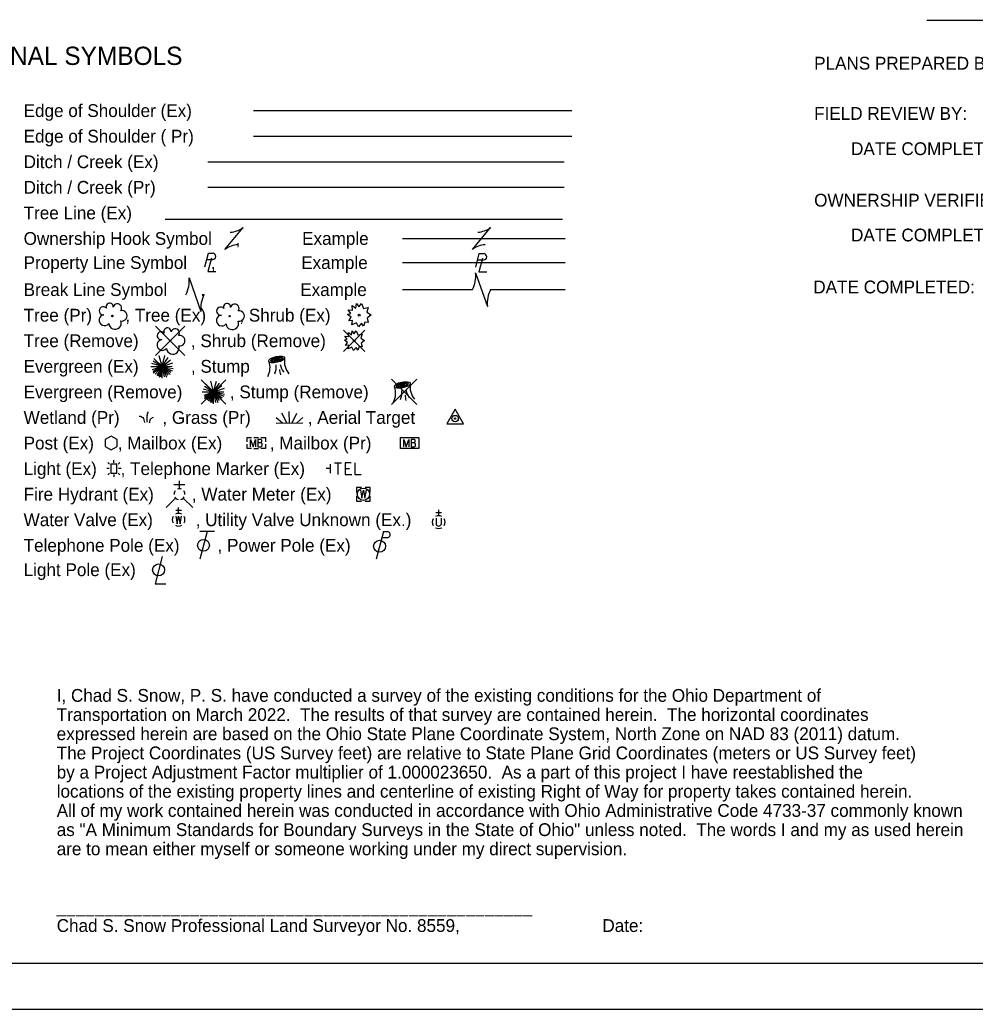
# Model space of a CAD drawing. Extents: x 0 to 59.1, y -2.4 to 22.
# Drawn here: x 16.87 to 27.33, y 0 to 10.83 of the extents above; entities that cross this region are included whole.
import ezdxf

# ---------------------------------------------------------------- set-up
doc = ezdxf.new("R2010")
doc.units = 0
for name, color, linetype in [('SH_Border', 7, 'Continuous'), ('SH_Cut_Line', 7, 'Continuous'), ('SH_Text', 7, 'Continuous')]:
    doc.layers.add(name, color=color, linetype=linetype)

msp = doc.modelspace()

# ---------------------------------------------------------------- linework, layer by layer
at = {"layer": 'SH_Border'}
msp.add_lwpolyline([(1.5, 21.5), (33.5, 21.5), (33.5, 0.5), (1.5, 0.5)], close=True, dxfattribs=at)
at = {"layer": 'SH_Cut_Line'}
msp.add_lwpolyline([(0, 0), (34, 0), (34, 22), (0, 22)], close=True, dxfattribs=at)
at = {"layer": 'SH_Text'}
for p, q in [((26.802, 10.829), (30.732, 10.829)), ((19.433, 9.839), (22.917, 9.839)), ((19.433, 9.559), (22.917, 9.559)), ((18.933, 9.279), (22.833, 9.279)), ((18.933, 8.999), (22.833, 8.999)), ((18.465, 8.649), (22.815, 8.649)), ((19.12, 8.319), (19.32, 8.559)), ((21.829, 8.319), (22.029, 8.559)), ((19.22, 8.439), (19.22, 8.439)), ((21.063, 8.439), (22.845, 8.439)), ((21.929, 8.439), (21.929, 8.439)), ((18.921, 8.208), (18.986, 8.208)), ((18.961, 8.177), (18.961, 8.177)), ((21.063, 8.175), (22.845, 8.175)), ((21.886, 8.204), (21.951, 8.204)), ((21.926, 8.173), (21.926, 8.173)), ((21.864, 8.063), (21.994, 7.695)), ((18.728, 8.008), (18.858, 7.64)), ((18.793, 7.824), (18.793, 7.824)), ((21.063, 7.879), (21.829, 7.879)), ((21.929, 7.879), (21.929, 7.879)), ((22.029, 7.879), (22.845, 7.879)), ((18.361, 7.48), (18.682, 7.159)), ((18.682, 7.48), (18.361, 7.159)), ((20.42, 7.435), (20.652, 7.203)), ((20.652, 7.435), (20.42, 7.203)), ((18.521, 7.319), (18.521, 7.319)), ((20.536, 7.319), (20.536, 7.319)), ((18.432, 7.039), (18.401, 7.154)), ((18.432, 7.039), (18.463, 7.156)), ((18.432, 7.039), (18.321, 7.069)), ((18.432, 7.039), (18.334, 7.096)), ((18.432, 7.039), (18.344, 7.126)), ((18.432, 7.039), (18.498, 7.136)), ((18.432, 7.039), (18.523, 7.109)), ((18.432, 7.039), (18.55, 7.079)), ((18.308, 7.039), (18.432, 7.039)), ((18.432, 7.039), (18.324, 7)), ((18.432, 7.039), (18.332, 6.982)), ((18.432, 7.039), (18.334, 6.964)), ((18.432, 7.039), (18.358, 6.952)), ((18.432, 7.039), (18.374, 6.939)), ((18.432, 7.039), (18.39, 6.93)), ((18.432, 7.039), (18.4, 6.918)), ((18.432, 7.039), (18.418, 6.924)), ((18.432, 7.039), (18.544, 7.041)), ((18.432, 6.908), (18.432, 7.039)), ((18.432, 7.039), (18.455, 6.923)), ((18.432, 7.039), (18.48, 6.922)), ((18.432, 7.039), (18.495, 6.944)), ((18.432, 7.039), (18.521, 6.951)), ((18.432, 7.039), (18.527, 6.975)), ((18.432, 7.039), (18.543, 6.99)), ((18.432, 7.039), (18.552, 7.015)), ((19.705, 7.039), (19.705, 7.039)), ((18.862, 6.893), (19.129, 6.626)), ((19.129, 6.893), (18.862, 6.626)), ((18.996, 6.759), (18.908, 6.846)), ((18.996, 6.759), (18.965, 6.875)), ((18.996, 6.759), (19.027, 6.877)), ((18.996, 6.759), (19.062, 6.856)), ((18.996, 6.759), (19.087, 6.829)), ((20.942, 6.898), (21.22, 6.62)), ((21.22, 6.898), (20.942, 6.62)), ((18.872, 6.759), (18.996, 6.759)), ((18.996, 6.759), (18.885, 6.789)), ((18.996, 6.759), (18.888, 6.72)), ((18.996, 6.759), (18.896, 6.702)), ((18.996, 6.759), (18.898, 6.817)), ((18.996, 6.759), (18.898, 6.684)), ((18.996, 6.759), (18.922, 6.673)), ((18.996, 6.759), (18.938, 6.659)), ((18.996, 6.759), (18.954, 6.651)), ((18.996, 6.759), (18.964, 6.638)), ((18.996, 6.759), (18.982, 6.644)), ((18.996, 6.759), (19.114, 6.799)), ((18.996, 6.759), (19.108, 6.761)), ((18.996, 6.628), (18.996, 6.759)), ((18.996, 6.759), (19.019, 6.643)), ((18.996, 6.759), (19.044, 6.642)), ((18.996, 6.759), (19.059, 6.664)), ((18.996, 6.759), (19.085, 6.671)), ((18.996, 6.759), (19.091, 6.695)), ((18.996, 6.759), (19.107, 6.711)), ((18.996, 6.759), (19.116, 6.735)), ((18.996, 6.759), (18.996, 6.759)), ((21.081, 6.759), (21.081, 6.759)), ((21.081, 6.759), (21.081, 6.759)), ((19.797, 6.419), (19.745, 6.525)), ((19.827, 6.419), (19.825, 6.545)), ((19.857, 6.42), (19.906, 6.527)), ((19.749, 6.418), (19.68, 6.475)), ((19.681, 6.417), (19.973, 6.421)), ((19.906, 6.42), (19.973, 6.479)), ((19.438, 6.26), (19.489, 6.26)), ((19.464, 6.199), (19.464, 6.199)), ((21.142, 6.199), (21.142, 6.199)), ((19.438, 6.138), (19.489, 6.138)), ((17.856, 5.968), (17.838, 5.986)), ((17.904, 5.983), (17.904, 6.01)), ((17.971, 5.986), (17.952, 5.968)), ((20.277, 5.869), (20.277, 5.969)), ((17.852, 5.92), (17.826, 5.92)), ((17.856, 5.871), (17.838, 5.852)), ((17.904, 5.919), (17.904, 5.919)), ((17.904, 5.855), (17.904, 5.829)), ((17.971, 5.852), (17.952, 5.871)), ((17.983, 5.92), (17.956, 5.92)), ((20.277, 5.919), (20.227, 5.919)), ((18.682, 5.742), (18.562, 5.742)), ((18.622, 5.699), (18.622, 5.785)), ((18.623, 5.639), (18.623, 5.639)), ((18.623, 5.639), (18.623, 5.639)), ((20.636, 5.639), (20.636, 5.639)), ((18.58, 5.597), (18.476, 5.493)), ((18.665, 5.597), (18.769, 5.493)), ((18.645, 5.461), (18.582, 5.461)), ((18.613, 5.429), (18.613, 5.493)), ((21.491, 5.435), (21.428, 5.435)), ((21.46, 5.403), (21.46, 5.466)), ((18.613, 5.359), (18.613, 5.359)), ((21.432, 5.376), (21.432, 5.307)), ((21.46, 5.333), (21.46, 5.333)), ((21.487, 5.376), (21.487, 5.307)), ((19.006, 5.229), (18.846, 5.229)), ((18.926, 5.229), (18.846, 4.929)), ((20.855, 5.229), (20.775, 4.929)), ((20.855, 5.229), (20.898, 5.229)), ((20.838, 5.165), (20.898, 5.165))]:
    msp.add_line(p, q, dxfattribs=at)
for points in [[(18.9, 8.129), (18.939, 8.277), (18.99, 8.277)], [(21.865, 8.125), (21.904, 8.273), (21.956, 8.273)], [(18.974, 8.225), (18.935, 8.077), (19.022, 8.077)], [(21.94, 8.221), (21.9, 8.073), (21.988, 8.073)], [(20.585, 7.69), (20.615, 7.726), (20.636, 7.674), (20.69, 7.683), (20.673, 7.632), (20.72, 7.602), (20.678, 7.566), (20.69, 7.52), (20.652, 7.523), (20.636, 7.478), (20.615, 7.512), (20.581, 7.472), (20.559, 7.516), (20.508, 7.494), (20.518, 7.541), (20.477, 7.537), (20.501, 7.577), (20.463, 7.605), (20.5, 7.618), (20.469, 7.659), (20.516, 7.653), (20.514, 7.705), (20.552, 7.677), (20.562, 7.726), (20.585, 7.69)], [(20.532, 7.396), (20.558, 7.427), (20.576, 7.383), (20.622, 7.39), (20.608, 7.347), (20.648, 7.322), (20.611, 7.291), (20.622, 7.252), (20.59, 7.255), (20.576, 7.216), (20.558, 7.245), (20.529, 7.211), (20.511, 7.248), (20.468, 7.23), (20.476, 7.27), (20.441, 7.267), (20.461, 7.3), (20.429, 7.324), (20.46, 7.335), (20.434, 7.37), (20.474, 7.365), (20.473, 7.409), (20.505, 7.385), (20.513, 7.427), (20.532, 7.396)], [(17.811, 6.162), (17.876, 6.124), (17.941, 6.162), (17.941, 6.237), (17.876, 6.274), (17.811, 6.237), (17.811, 6.162)], [(19.364, 6.212), (19.364, 6.26), (19.413, 6.26)], [(19.413, 6.138), (19.364, 6.138), (19.364, 6.187)], [(19.399, 6.159), (19.399, 6.239), (19.428, 6.159), (19.456, 6.239), (19.456, 6.159)], [(19.515, 6.203), (19.518, 6.206), (19.52, 6.208), (19.521, 6.21), (19.522, 6.211), (19.523, 6.213), (19.524, 6.215), (19.525, 6.22), (19.525, 6.222), (19.525, 6.224), (19.525, 6.228), (19.523, 6.231), (19.521, 6.234), (19.518, 6.236), (19.516, 6.237), (19.515, 6.238), (19.511, 6.239), (19.481, 6.239), (19.481, 6.159), (19.515, 6.159), (19.52, 6.162), (19.523, 6.165), (19.526, 6.17), (19.528, 6.176), (19.529, 6.181), (19.529, 6.185), (19.528, 6.189), (19.525, 6.194), (19.522, 6.198), (19.515, 6.203), (19.481, 6.203)], [(19.514, 6.26), (19.564, 6.26), (19.564, 6.212)], [(19.564, 6.187), (19.564, 6.138), (19.514, 6.138)], [(21.077, 6.159), (21.077, 6.239), (21.106, 6.159), (21.134, 6.239), (21.134, 6.159)], [(21.193, 6.203), (21.196, 6.206), (21.198, 6.208), (21.2, 6.21), (21.2, 6.211), (21.201, 6.213), (21.202, 6.215), (21.203, 6.22), (21.203, 6.222), (21.203, 6.224), (21.203, 6.228), (21.201, 6.231), (21.2, 6.234), (21.196, 6.236), (21.194, 6.237), (21.193, 6.238), (21.19, 6.239), (21.159, 6.239), (21.159, 6.159), (21.193, 6.159), (21.198, 6.162), (21.201, 6.165), (21.205, 6.17), (21.207, 6.176), (21.207, 6.181), (21.207, 6.185), (21.206, 6.189), (21.203, 6.194), (21.2, 6.198), (21.193, 6.203), (21.159, 6.203)], [(20.318, 5.981), (20.396, 5.981)], [(20.357, 5.981), (20.357, 5.856)], [(20.503, 5.981), (20.435, 5.981), (20.435, 5.856), (20.508, 5.856)], [(20.542, 5.981), (20.542, 5.856), (20.61, 5.856)], [(20.435, 5.919), (20.483, 5.919)], [(20.616, 5.714), (20.561, 5.714), (20.561, 5.659)], [(20.603, 5.684), (20.619, 5.594), (20.636, 5.684), (20.653, 5.594), (20.669, 5.684)], [(20.711, 5.659), (20.711, 5.714), (20.656, 5.714)], [(20.561, 5.619), (20.561, 5.564), (20.616, 5.564)], [(20.656, 5.564), (20.711, 5.564), (20.711, 5.619)], [(18.582, 5.4), (18.597, 5.314), (18.613, 5.4), (18.629, 5.314), (18.645, 5.4)], [(18.434, 4.958), (18.355, 4.659), (18.473, 4.659)]]:
    msp.add_lwpolyline(points, dxfattribs=at)
for points in [[(21.55, 6.409), (21.73, 6.409), (21.64, 6.57)], [(21.042, 6.26), (21.242, 6.26), (21.242, 6.138), (21.042, 6.138)], [(17.871, 5.869), (17.938, 5.869), (17.938, 5.969), (17.871, 5.969)]]:
    msp.add_lwpolyline(points, close=True, dxfattribs=at)
for centre, radius in [((17.888, 7.591), 0.0084), ((19.173, 7.588), 0.0072), ((20.589, 7.599), 0.0115), ((18.521, 7.319), 0.0072), ((20.536, 7.319), 0.00979), ((21.64, 6.467), 0.035), ((21.64, 6.467), 0.008), ((20.636, 5.639), 0.0675), ((18.886, 5.079), 0.065), ((20.813, 5.069), 0.065), ((18.394, 4.81), 0.065)]:
    msp.add_circle(centre, radius, dxfattribs=at)
for centre, radius, start, end in [((19.162, 8.774), 0.267, 273.6945, 306.337), ((21.871, 8.774), 0.267, 273.6945, 306.337), ((19.279, 8.104), 0.267, 93.6945, 126.337), ((21.987, 8.104), 0.267, 93.6945, 126.337), ((18.985, 8.243), 0.0345, 270.471, 81.3281), ((21.951, 8.239), 0.0345, 270.471, 81.3281), ((21.532, 8.031), 0.334, 332.9422, 5.5848), ((18.396, 7.975), 0.334, 332.9422, 5.5848), ((19.19, 7.672), 0.334, 152.9422, 185.5848), ((22.326, 7.728), 0.334, 152.9422, 185.5848), ((17.859, 7.692), 0.0395, 354.0047, 205.9741), ((17.943, 7.676), 0.0466, 323.83, 165.0376), ((19.143, 7.689), 0.0395, 354.0047, 205.9741), ((19.228, 7.673), 0.0466, 323.83, 165.0376), ((17.803, 7.545), 0.0592, 96.1722, 320.5737), ((17.789, 7.647), 0.0441, 39.0625, 279.5412), ((17.992, 7.592), 0.0574, 259.1453, 101.4596), ((19.087, 7.541), 0.0592, 96.1722, 320.5737), ((19.074, 7.644), 0.0441, 39.0625, 279.5412), ((19.277, 7.589), 0.0574, 259.1453, 101.4596), ((17.917, 7.513), 0.0685, 184.9476, 19.4572), ((19.201, 7.509), 0.0685, 184.9476, 19.4572), ((18.422, 7.375), 0.0441, 39.0625, 279.5412), ((18.492, 7.42), 0.0395, 354.0047, 205.9741), ((18.576, 7.404), 0.0466, 323.83, 165.0376), ((18.625, 7.32), 0.0574, 259.1453, 101.4596), ((18.436, 7.273), 0.0592, 96.1722, 320.5737), ((18.55, 7.241), 0.0685, 184.9476, 19.4572), ((19.414, 7.022), 0.2, 331.5338, 20.9269), ((19.429, 7.04), 0.253, 340.7938, 3.5481), ((20.031, 7.142), 0.316, 194.9653, 212.1216), ((19.986, 7.096), 0.215, 171.4106, 219.9194), ((19.901, 6.999), 0.182, 178.7926, 197.1224), ((21.361, 6.816), 0.215, 171.4106, 219.9194), ((20.789, 6.742), 0.2, 331.5338, 20.9269), ((20.805, 6.76), 0.253, 340.7938, 3.5481), ((21.276, 6.719), 0.182, 178.7926, 197.1224), ((21.406, 6.862), 0.316, 194.9653, 212.1216), ((18.623, 5.639), 0.06, 140.021, 184.0629), ((18.623, 5.639), 0.06, 68.1395, 112.038), ((18.623, 5.639), 0.06, 356.0165, 39.9889), ((18.623, 5.639), 0.06, 211.8788, 255.8479), ((18.623, 5.639), 0.06, 283.8239, 329.9097), ((18.613, 5.359), 0.07, 60.0184, 120.0157), ((18.613, 5.359), 0.07, 150.0184, 209.9816), ((18.613, 5.359), 0.07, 330.0184, 29.9816), ((21.46, 5.333), 0.07, 150.0184, 209.9816), ((21.46, 5.333), 0.07, 60.0184, 120.0157), ((21.46, 5.333), 0.07, 330.0184, 29.9816), ((18.613, 5.359), 0.07, 239.9843, 299.9816), ((20.899, 5.197), 0.0319, 268.8767, 91.1233), ((21.46, 5.333), 0.07, 239.9843, 299.9816), ((21.459, 5.32), 0.03, 205.1924, 334.8076)]:
    msp.add_arc(centre, radius, start, end, dxfattribs=at)
for centre, major_axis in [((19.687, 7.115), (0.0868, 0.0187)), ((19.687, 7.115), (0.0651, 0.0141)), ((19.687, 7.115), (0.0488, 0.0105)), ((19.687, 7.115), (0.0275, 0.0059)), ((19.687, 7.115), (0.0154, 0.0033)), ((21.062, 6.835), (0.0868, 0.0187)), ((21.062, 6.835), (0.0651, 0.0141)), ((21.062, 6.835), (0.0488, 0.0105)), ((21.062, 6.835), (0.0275, 0.0059)), ((21.062, 6.835), (0.0154, 0.0033))]:
    msp.add_ellipse(centre, major_axis=major_axis, ratio=0.36865, dxfattribs=at)
for points in [[(18.268, 6.428), (18.268, 6.475), (18.274, 6.52), (18.283, 6.54)], [(18.18, 6.495), (18.222, 6.477), (18.24, 6.424)], [(18.296, 6.421), (18.307, 6.459), (18.337, 6.483)]]:
    msp.add_spline(points, degree=3, dxfattribs=at)

# ---------------------------------------------------------------- texts
for s, height, p in [('CONVENTIONAL SYMBOLS', 0.2, (15.178, 10.339)), ('PLANS PREPARED BY:', 0.14, (25.57, 10.288)), ('Edge of Shoulder (Ex)', 0.14, (16.917, 9.769)), ('FIELD REVIEW BY:', 0.14, (25.57, 9.738)), ('Edge of Shoulder ( Pr)', 0.14, (16.917, 9.489)), ('DATE COMPLETED:   ', 0.14, (25.974, 9.352)), ('Ditch / Creek (Ex)', 0.14, (16.917, 9.209)), ('Ditch / Creek (Pr)', 0.14, (16.917, 8.929)), ('OWNERSHIP VERIFIED BY:', 0.14, (25.57, 8.788)), ('Tree Line (Ex)', 0.14, (16.917, 8.649)), ('Ownership Hook Symbol     ,             Example', 0.14, (16.917, 8.369)), ('DATE COMPLETED:', 0.14, (25.974, 8.407)), ('Property Line Symbol     ,                  Example', 0.14, (16.917, 8.105)), ('Break Line Symbol       ,                    Example', 0.14, (16.917, 7.809)), ('DATE COMPLETED:', 0.14, (25.561, 7.838)), ('Tree (Pr)       , Tree (Ex)       , Shrub (Ex)', 0.14, (16.917, 7.529)), ('Tree (Remove)           , Shrub (Remove)', 0.14, (16.917, 7.249)), ('Evergreen (Ex)           , Stump ', 0.14, (16.917, 6.969)), ('Evergreen (Remove)          , Stump (Remove)', 0.14, (16.917, 6.689)), ('Wetland (Pr)         , Grass (Pr)            , Aerial Target    ', 0.14, (16.917, 6.409)), ('Post (Ex)     , Mailbox (Ex)          , Mailbox (Pr)', 0.14, (16.917, 6.129)), ('Light (Ex)     , Telephone Marker (Ex)     ', 0.14, (16.917, 5.849)), ('Fire Hydrant (Ex)        , Water Meter (Ex)', 0.14, (16.917, 5.569)), ('Water Valve (Ex)         , Utility Valve Unknown (Ex.)', 0.14, (16.917, 5.289)), ('Telephone Pole (Ex)        , Power Pole (Ex)', 0.14, (16.917, 5.009)), ('Light Pole (Ex)     ', 0.14, (16.917, 4.742)), ('I, Chad S. Snow, P. S. have conducted a survey of the existing conditions for the Ohio Department of', 0.14, (17.279, 3.366)), ('Transportation on March 2022.  The results of that survey are contained herein.  The horizontal coordinates', 0.14, (17.279, 3.156)), ('expressed herein are based on the Ohio State Plane Coordinate System, North Zone on NAD 83 (2011) datum.', 0.14, (17.279, 2.946)), ('The Project Coordinates (US Survey feet) are relative to State Plane Grid Coordinates (meters or US Survey feet)', 0.14, (17.279, 2.736)), ('by a Project Adjustment Factor multiplier of 1.000023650.  As a part of this project I have reestablished the', 0.14, (17.279, 2.526)), ('locations of the existing property lines and centerline of existing Right of Way for property takes contained herein.  ', 0.14, (17.279, 2.316)), ('All of my work contained herein was conducted in accordance with Ohio Administrative Code 4733-37 commonly known', 0.14, (17.279, 2.106)), ('as "A Minimum Standards for Boundary Surveys in the State of Ohio" unless noted.  The words I and my as used herein', 0.14, (17.279, 1.896)), ('are to mean either myself or someone working under my direct supervision.', 0.14, (17.279, 1.686)), ('__________________________________________________', 0.14, (17.279, 1.056)), ('Chad S. Snow Professional Land Surveyor No. 8559,                              Date:                ', 0.14, (17.279, 0.846))]:
    msp.add_text(s, height=height, dxfattribs=at).set_placement(p)

doc.saveas('drawing.dxf')
